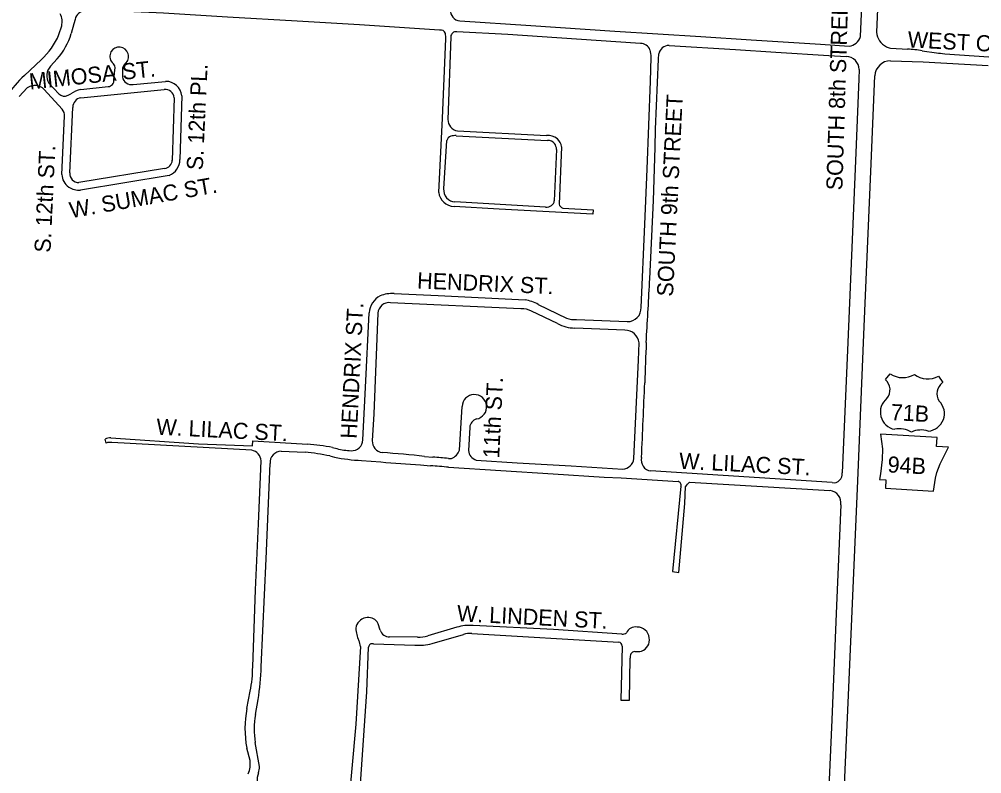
# Model space of a CAD drawing. Extents: x 0 to 712119, y 0 to 761125.
# Drawn here: x 683343 to 686331, y 727282 to 729625 of the extents above; entities that cross this region are included whole.
import ezdxf

# ---------------------------------------------------------------- set-up
doc = ezdxf.new("R2010")
doc.units = 0
for name, color, linetype in [('HWY signs', 7, 'Continuous'), ('PAVED ROADS', 7, 'Continuous'), ('street names', 7, 'Continuous')]:
    doc.layers.add(name, color=color, linetype=linetype)

msp = doc.modelspace()

# ---------------------------------------------------------------- linework, layer by layer
at = {"layer": 'HWY signs'}
for points in [[(686031.9, 728505.9), (686047, 728524.3)], [(686121.9, 728522.3), (686121.9, 728522.3)], [(686196.6, 728516.5), (686209.7, 728496.6)]]:
    msp.add_lwpolyline(points, dxfattribs=at)
msp.add_lwpolyline([(686180.8, 728160), (686187.2, 728200.3), (686191.9, 728218), (686202.2, 728244.8), (686212.9, 728267.2), (686227.7, 728296.3), (686190.8, 728298.5), (686192.4, 728325.9), (686016.9, 728336.5), (686022.4, 728290.9), (686021.8, 728257.8), (686016.3, 728213.5), (686013.4, 728195.9), (686033.5, 728194.7), (686032, 728168.9)], close=True, dxfattribs=at)
for centre, radius, start, end in [((686085.9, 728580.5), 68.4, 235.2382, 301.7199), ((686163.7, 728576.4), 68.4, 232.3011, 298.7827), ((686004.8, 728474.5), 41.5, 320.1078, 49.1208), ((686233.4, 728462.6), 41.5, 124.9002, 213.9131), ((686070.6, 728405.4), 54.5, 128.6765, 259.9158), ((686160.7, 728400.7), 54.5, 274.1051, 45.3444), ((686075.4, 728279.6), 73.6, 59.7374, 101.2498), ((686142.8, 728276.1), 73.6, 72.7711, 114.2835)]:
    msp.add_arc(centre, radius, start, end, dxfattribs=at)
at = {"layer": 'PAVED ROADS'}
for points in [[(686046.7, 730595.3), (686025.5, 730084.2), (686004.2, 729584.7)], [(685954.7, 729571.2), (685970.2, 729923), (685981, 730173.6)], [(684647.4, 729591.7), (684398.7, 729608), (684205.5, 729619.6), (683989, 729632.1), (683790, 729643.5), (683606.6, 729652.3)], [(683515.8, 729624.8), (683512.5, 729611.2), (683504.2, 729580.8)], [(684710.1, 729620.4), (684930.7, 729605.5), (685191.5, 729588.5), (685458.9, 729571.1), (685615.4, 729560.8), (685830.3, 729547.4), (685919, 729541.8)], [(683465.8, 729577.9), (683474.4, 729605.1)], [(684644.9, 729087.4), (684656.5, 729317.8), (684667, 729564.4)], [(684682.4, 729570.8), (684673.2, 729314.2)], [(685271.6, 729549.8), (685072.7, 729563.1), (684859.7, 729577.6), (684701.3, 729586.4)], [(685360.2, 729543.5), (685566.9, 729531.4), (685692.1, 729522.9), (685856.6, 729512.8), (685910.4, 729509.1)], [(686047.3, 729535.6), (686101, 729532.5)], [(683358.5, 729450.2), (683410.5, 729499.4)], [(683460.6, 729502.3), (683439.5, 729479)], [(685273.2, 728730.2), (685285.2, 728988.8), (685291.7, 729159.3), (685302.8, 729433.2), (685304.6, 729506.1)], [(685300.2, 728819.1), (685312.3, 729062.4), (685317.3, 729226.7), (685318, 729283.6), (685327.3, 729501.6), (685328.3, 729517.3)], [(686146, 729527.1), (686190.3, 729521)], [(686215.9, 729518.1), (686610.9, 729490.3)], [(686047.6, 729496.3), (686148.9, 729492.4), (686351, 729481.2)], [(683636.7, 729437), (683639.7, 729467.2)], [(683663.1, 729467.5), (683663, 729445.9)], [(685897.4, 726962.1), (685900, 727132.2), (685916.9, 727525.8), (685931.5, 727858.7), (685946, 728192.1), (685966.2, 728671.5), (685987, 729152), (685998.6, 729449.7)], [(685950.3, 729469), (685949.7, 729440.6), (685938.8, 729185.3), (685914.3, 728597.5), (685898.1, 728216.1)], [(683367.4, 729411.9), (683342.6, 729385.5)], [(683434.8, 729426.5), (683465.1, 729393.8)], [(683533.9, 729406.9), (683618.8, 729416)], [(683696.8, 729422.9), (683797, 729432.1)], [(683475.6, 729345.6), (683420, 729407.4)], [(683494, 729388.9), (683502.8, 729393.3)], [(683533.7, 729381.3), (683792.9, 729407.4)], [(683823.9, 729381.5), (683817.8, 729187)], [(683847.6, 729387.2), (683841.5, 729189.5)], [(683499.4, 729147.8), (683509.1, 729351.4)], [(683474.9, 729143), (683482.9, 729323.7)], [(684699.4, 729263.6), (684983, 729249)], [(684703, 729278.2), (684979.5, 729264.6)], [(684660.4, 729098.2), (684670.1, 729248.6)], [(685011, 729220.6), (685003.5, 729061.5)], [(685025.9, 729229.4), (685019.1, 729051.3)], [(683793.6, 729161.5), (683527.9, 729118.1)], [(683808.1, 729139.9), (683533.2, 729094.8)], [(684976.6, 729041.6), (684695.4, 729057.9)], [(685030.3, 729038.9), (685124.5, 729032.8), (685123.9, 729019.4), (684832.8, 729035.3), (684692.6, 729043.6)], [(684506.2, 728773.1), (684643, 728766.9), (684913.7, 728753.4)], [(684900.2, 728726.1), (684495.2, 728745)], [(684953.8, 728739.6), (685041.9, 728697.3)], [(684409.7, 728318.6), (684418, 728481.4), (684429.4, 728713.1)], [(684456.1, 728712.8), (684443.2, 728400.2), (684438.7, 728316.4)], [(685014, 728680.6), (684933.5, 728718.8), (684933.5, 728718.8)], [(685072.9, 728692.8), (685230.5, 728686.4)], [(685223.3, 728659.8), (685067.6, 728666)], [(685289.3, 728621.5), (685289.9, 728633.1)], [(685251.3, 728260.8), (685265.6, 728566.1), (685267.2, 728620.2)], [(684710, 728287.4), (684717.5, 728422.9)], [(684741.4, 728357.8), (684737.6, 728286)], [(683612.9, 728309.1), (683609.6, 728321.4)], [(683627.2, 728325.2), (683899.6, 728306.7), (684066.8, 728300.2), (684068, 728315.9), (684237.1, 728305.9)], [(684064.6, 728287.1), (683630, 728310.4)], [(684156.2, 728284.1), (684229.9, 728280.9)], [(684315.5, 728295.4), (684328.8, 728292)], [(684067.5, 727614.5), (684076.2, 727853.4), (684085.1, 728058.4), (684093.8, 728254.2)], [(684093.7, 727614.5), (684109.1, 727949.2), (684121.2, 728245.2)], [(684307.3, 728269.1), (684321.2, 728265.4)], [(684405, 728254.9), (684465.5, 728250.3)], [(684601.1, 728267.3), (684626.5, 728265.2)], [(684675.5, 728261.5), (684684.6, 728260.9)], [(684761.6, 728256.4), (684888.4, 728248.1), (685056, 728238.8), (685216.4, 728228)], [(684588.3, 728241.7), (684619.4, 728238.7)], [(684675.7, 728234.1), (684999.9, 728213), (685158.6, 728203.3), (685211.3, 728200.7), (685388.6, 728189.9)], [(685866.7, 728186.3), (685303, 728222.5)], [(685423.5, 728187.9), (685859.8, 728161.8)], [(685396.8, 728174.7), (685371.1, 727910.1), (685390.1, 727907.5), (685409, 728121.8), (685411.7, 728174.4)], [(685893.8, 728117.1), (685880.1, 727804.8), (685865.4, 727449.6), (685851, 727123.7), (685837.4, 726957)], [(684701.7, 727737), (684611.3, 727710.5)], [(685214, 727715.9), (685001.6, 727729.6), (684751.8, 727742.5)], [(684579.1, 727705.9), (684492.5, 727707.8)], [(684624.2, 727686.2), (684722, 727714.6)], [(684747.6, 727717.8), (685204.1, 727690.5)], [(684401.7, 727677.7), (684387.3, 727435.9), (684362.1, 727149.1), (684349.2, 726989.3)], [(684442.6, 727685.4), (684570.7, 727681.6)], [(685214.7, 727678.7), (685210.3, 727510.2), (685237.7, 727510.2), (685239.4, 727640.6)], [(684399.8, 727215.2), (684404.5, 727281), (684422.1, 727536.7), (684427, 727675.4)], [(684049.5, 727484.8), (684059.4, 727538.6)], [(684075.9, 727465.8), (684084, 727512.8)], [(684089, 727305.1), (684075.1, 727379)], [(684059.3, 727322.9), (684049, 727361.6)]]:
    msp.add_lwpolyline(points, dxfattribs=at)
for centre, radius, start, end in [((683550.9, 729616.4), 36.1, 93.3782, 166.4927), ((684712.8, 729651.6), 31.4, 175.3366, 265.124), ((683427.2, 729617.3), 48.7, 345.4817, 29.8437), ((684649.9, 729574.3), 17.6, 23.7081, 98.1417), ((683271.9, 729655.8), 209, 311.551, 338.1106), ((683300.5, 729642.5), 212.8, 318.7789, 343.1258), ((680663, 729337.3), 4010.5, 3.2464, 3.4886), ((684699.1, 729569.9), 16.7, 82.4194, 176.8426), ((685915.1, 729582.9), 41.3, 275.4569, 343.5556), ((686062.7, 729591.3), 58.9, 186.4057, 241.6927), ((683652.6, 729509.2), 29.4, 311.2453, 149.0506), ((685273.2, 729520.4), 29.4, 19.4429, 93.2025), ((685175.9, 729499.2), 128.9, 3.0832, 13.9268), ((685359, 729512.5), 31.1, 87.8715, 171.2003), ((686053.4, 729577.1), 42, 243.7326, 261.6122), ((686073.2, 729112.2), 421.2, 80.0583, 86.2203), ((683655.2, 729510.1), 31.2, 152.8872, 218.3111), ((685910, 729468.8), 40.3, 0.2353, 89.5165), ((686253.6, 729960.1), 443.6, 261.8038, 265.1231), ((683471.9, 729449.7), 43.8, 137.8684, 211.9541), ((683618.2, 729472.5), 22.2, 346.1397, 55.7912), ((683687.9, 729468.2), 24.8, 130.024, 181.4929), ((686048.9, 729445.9), 50.4, 91.4294, 175.633), ((683680.8, 729114.1), 465.7, 133.7991, 144.0711), ((683690.7, 729450.3), 28, 188.9614, 282.4676), ((683391.1, 729378.8), 40.7, 44.6695, 125.4691), ((683617.7, 729435), 19.1, 273.4958, 5.8602), ((683798.2, 729382.5), 49.6, 5.4875, 91.3662), ((683483, 729411.9), 25.5, 225.2155, 295.6012), ((683548.9, 729330.3), 78.1, 101.0283, 126.1868), ((683538.7, 729352.1), 29.6, 99.6444, 181.2845), ((683794.5, 729377.8), 29.6, 7.1636, 93.1916), ((683456.7, 729327.1), 26.4, 352.6506, 44.3072), ((684710.9, 729315), 37.7, 181.3002, 257.9821), ((684688.2, 729244.3), 18.5, 106.5277, 166.6914), ((684696.2, 729207.5), 56.2, 86.7719, 103.7273), ((684981.5, 729213.5), 51.1, 51.4515, 92.2485), ((684983.2, 729220.8), 28.2, 40.0347, 90.3462), ((684973.8, 729218.2), 37.3, 3.7686, 33.8787), ((684992.8, 729227.5), 33.2, 3.3996, 51.8101), ((683789, 729190.1), 29, 279.1283, 353.9122), ((683787.3, 729189.9), 54.1, 292.5453, 359.6333), ((683523.9, 729144.3), 49, 181.5425, 235.456), ((683527.4, 729146.2), 28.1, 176.6596, 271.0075), ((683527.9, 729152.9), 58.4, 236.9976, 275.2312), ((684694.6, 729093.7), 50.1, 187.1772, 267.6451), ((684697.9, 729095.5), 37.7, 175.9101, 266.087), ((684987.5, 729061.2), 16, 299.1293, 1.1144), ((685034.1, 729053.6), 15.2, 188.8167, 255.347), ((684978.6, 729068.7), 27.2, 265.7796, 307.7762), ((653757.6, 730479.1), 31586.3, 356.64944, 356.98738), ((684493.8, 728709.5), 64.5, 118.5693, 176.7899), ((684500.8, 728668.1), 105.2, 87.0861, 111.0993), ((684899.5, 728646.9), 107.5, 59.6546, 82.4005), ((684491.2, 728710), 35.2, 83.4786, 175.3622), ((684902.4, 728655.9), 70.2, 63.7002, 91.7883), ((685232.1, 728727.6), 41.2, 267.8014, 3.6755), ((685066.3, 728756.4), 63.9, 247.6077, 275.9388), ((685069.3, 728778.5), 112.5, 240.5498, 269.1164), ((685222.4, 728614.7), 45.1, 7.0188, 88.9298), ((717731.2, 727319.2), 32468, 177.70121, 177.92296), ((661925.4, 729386.4), 23376.1, 357.24763, 357.81703), ((684755.6, 728421.4), 38.2, 280.0274, 177.8239), ((684771.5, 728355), 30.3, 107.6876, 174.6564), ((683625, 728292.7), 32.6, 86.1016, 118.1446), ((683623.6, 728282.6), 28.5, 77.0568, 111.9995), ((684145.1, 727319.7), 990.4, 80.0971, 84.67), ((684375.1, 728319.9), 34.6, 266.2203, 357.7821), ((684473.7, 728314.2), 35.1, 176.3664, 263.6086), ((684057.2, 728251.1), 36.7, 4.8359, 78.383), ((684157.7, 728247.6), 36.6, 92.2145, 183.6804), ((684120.1, 727305.5), 981.6, 79.0071, 83.5774), ((684374.8, 728450), 164.6, 253.7653, 269.3156), ((684298.1, 725680.8), 2604.2, 83.3188, 86.2191), ((684664.1, 728305.9), 49.4, 294.4347, 338.0994), ((684770, 728287.7), 32.4, 182.8787, 254.9082), ((684434.1, 728826.7), 572.6, 258.6239, 267.0845), ((685134, 736861.8), 8637.4, 265.56159, 266.37802), ((684496.2, 726233), 2036.3, 84.9474, 86.3295), ((685213.9, 728265.7), 37.7, 273.7406, 352.5797), ((685307.8, 728256.3), 34.2, 167.2196, 261.7986), ((683626, 715692.3), 12585.6, 85.21531, 85.47242), ((685871.3, 728212.8), 26.9, 260.1099, 7.0478), ((685385.9, 728178.7), 11.6, 340.1296, 76.73), ((685149.8, 728415.4), 355.9, 317.3886, 320.2705), ((685853.9, 728122), 40.2, 352.9669, 81.4525), ((684425, 727730.1), 37.3, 100.6857, 173.9987), ((684425.5, 727731.1), 36.4, 38.4269, 101.7771), ((684332.2, 727696.9), 134.4, 13.4157, 24.9945), ((684742, 727602.1), 140.8, 85.9899, 106.6202), ((685255.6, 727707.6), 30.5, 80.1962, 156.4943), ((685261.2, 727700), 37.7, 6.7783, 90.5279), ((684479.7, 727735.8), 91.8, 181.1671, 205.8619), ((684490.1, 727735.9), 28.2, 196.1135, 275.0038), ((684568.1, 727901.2), 195.6, 273.2235, 282.7657), ((684743.5, 727646.2), 71.7, 86.6894, 107.41), ((685215.5, 727736.6), 20.8, 265.7152, 305.744), ((684276.9, 727655.5), 126.8, 10.0676, 18.5062), ((684438.7, 727674.2), 11.8, 70.9599, 174.4211), ((684583.8, 727842.6), 161.5, 265.341, 284.492), ((685203, 727678.8), 11.7, 359.5556, 84.5655), ((685263.8, 727697.2), 35.5, 287.0966, 11.7156), ((685256.2, 727644.8), 17.3, 99.0176, 193.8677), ((685260.1, 727719.5), 58, 263.4795, 284.1475), ((683717.5, 727613.2), 349.9, 347.6954, 0.2203), ((683461, 727623.4), 632.7, 349.9305, 359.1909), ((684376.7, 727421.9), 333.2, 169.1113, 190.4218), ((684355, 727420), 282.9, 170.6816, 188.3363), ((683983.3, 727312.7), 76.7, 336.4952, 7.641), ((683999.7, 727310.8), 89.5, 343.0678, 356.3115), ((684141.9, 727262.3), 60.9, 158.3431, 186.6841)]:
    msp.add_arc(centre, radius, start, end, dxfattribs=at)

# ---------------------------------------------------------------- texts
at = {"layer": 'HWY signs'}
for s, p in [('71B', (686047.6, 728380.5)), ('94B', (686037.7, 728218.1))]:
    msp.add_text(s, height=50, rotation=357.0105, dxfattribs=at).set_placement(p)
at = {"layer": 'street names'}
for s, rotation, p in [('SOUTH 8th STREET', 88.2731, (685898.3, 729093.3)), ('WEST OLRICH STREET', 356.9997, (686099.9, 729538.1)), ('MIMOSA ST.', 5.9838, (683375.9, 729406.7)), ('S. 12th PL.', 87.3457, (683912.3, 729155.6)), ('SOUTH 9th STREET', 87.193, (685372.2, 728763.1)), ('S. 12th ST.', 87.3457, (683439.5, 728899.4)), ('W. SUMAC ST.', 9.9838, (683503.1, 729007)), ('HENDRIX ST.', 357.568, (684577.1, 728789.3)), ('HENDRIX ST.', 87.193, (684390.3, 728321.5)), ('11th ST.', 87.193, (684832.6, 728261)), ('W. LILAC ST.', 357.0768, (683767.2, 728335.4)), ('W. LILAC ST.', 357.0768, (685390.2, 728229.5)), ('W. LINDEN ST.', 357.0768, (684700.7, 727756))]:
    msp.add_text(s, height=50, rotation=rotation, dxfattribs=at).set_placement(p)

doc.saveas('drawing.dxf')
